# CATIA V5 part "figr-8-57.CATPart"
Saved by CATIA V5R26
Part number: Part1
Bounding box of the stored display mesh (mm): x -50.499 to 50.499, y -68.48 to 68.48, z -46 to 50
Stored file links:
  D:\_Deepak\CATIA\CATIA V5-6R2016_Deepak\Resources\Part files\Partfiles\c08_catia_v5_6r2016_prt\figr-8-57.CATPart
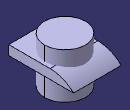
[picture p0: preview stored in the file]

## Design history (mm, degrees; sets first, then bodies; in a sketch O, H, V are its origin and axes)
Body1 (main body)
  Sketch1 on xy-plane, origin (0, 0, 0), H (1, 0, 0), V (0, 1, 0)
    line L1 (-50.499, 68.4797) -> (50.499, 68.4797)
    line L2 (50.499, 68.4797) -> (50.499, -68.4797)
    line L3 (50.499, -68.4797) -> (-50.499, -68.4797)
    line L4 (-50.499, -68.4797) -> (-50.499, 68.4797)
    axis line L5 (50.499, -68.4797) -> (-50.499, 68.4797)
    horizontal: L1 H, L3 H
    vertical: L2 V, L4 V
    midpoint: O L5
  Pad1: profile Sketch1, direction (0, 0, 1), length 20
  Fillet1: radius 71, on edge [face of Pad1 | face of Pad1]
Body2
  Sketch2 on xy-plane, origin (0, 0, 0), H (1, 0, 0), V (0, 1, 0)
    circle A1 centre (0, 0) radius 43.2524
    point P1 (0, 43.2524)
    coincidence: A1 P1, P1 V
  Pad2: profile Sketch2, direction (0, 0, 1), length 50, opposite side length 46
